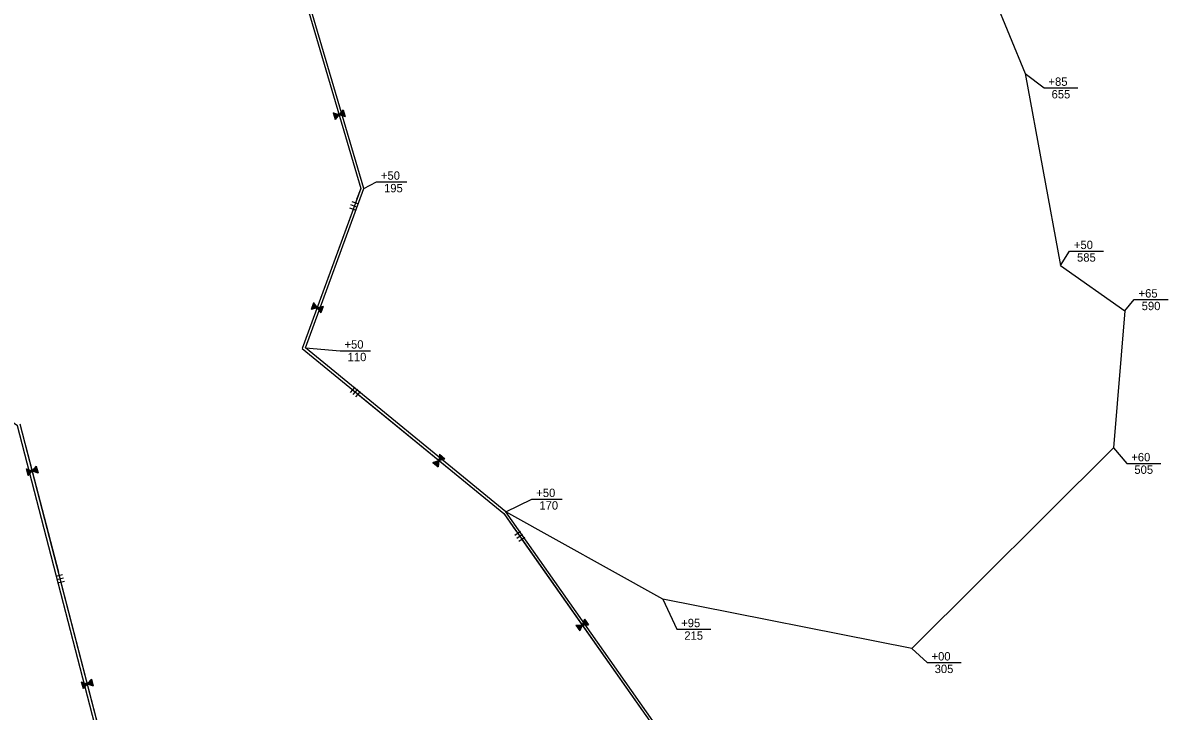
# Model space of a CAD drawing. Extents: x 979729 to 993523, y 1834148 to 1845433.
# Drawn here: x 980605 to 981425, y 1838851 to 1839343 of the extents above; entities that cross this region are included whole.
import ezdxf

# ---------------------------------------------------------------- set-up
doc = ezdxf.new("R2010")
doc.units = 0
for name, color, linetype in [('42', 7, 'Continuous'), ('51', 7, 'Continuous'), ('53', 7, 'Continuous'), ('R_Draft', 7, 'Continuous')]:
    doc.layers.add(name, color=color, linetype=linetype)

msp = doc.modelspace()

# ---------------------------------------------------------------- linework, layer by layer
at = {"layer": '42'}
for p, q in [((980795.43, 1839399), (980846.56, 1839224.93)), ((980833.94, 1839281.23), (980831.04, 1839277.77)), ((980832.76, 1839279.68), (980834.4, 1839279.17)), ((980832.86, 1839279.91), (980834.47, 1839279.41)), ((980833.01, 1839280.12), (980834.38, 1839279.69)), ((980833.2, 1839280.33), (980834.3, 1839279.98)), ((980833.4, 1839280.53), (980834.22, 1839280.27)), ((980833.55, 1839280.74), (980834.13, 1839280.56)), ((980833.75, 1839280.94), (980834.05, 1839280.85)), ((980833.9, 1839281.16), (980833.96, 1839281.14)), ((980826.74, 1839279.11), (980831.04, 1839277.77)), ((980826.81, 1839279.07), (980826.77, 1839279.02)), ((980827.05, 1839278.98), (980826.85, 1839278.73)), ((980827.32, 1839278.91), (980826.93, 1839278.45)), ((980827.57, 1839278.81), (980827.02, 1839278.16)), ((980827.84, 1839278.75), (980827.1, 1839277.87)), ((980828.11, 1839278.68), (980827.19, 1839277.58)), ((980828.36, 1839278.59), (980827.27, 1839277.29)), ((980828.86, 1839278.41), (980827.44, 1839276.72)), ((980828.56, 1839278.44), (980827.47, 1839277.13)), ((980829.1, 1839278.31), (980827.53, 1839276.43)), ((980829.39, 1839278.27), (980827.61, 1839276.14)), ((980829.62, 1839278.15), (980827.7, 1839275.85)), ((980829.91, 1839278.1), (980827.78, 1839275.56)), ((980830.15, 1839278.01), (980827.87, 1839275.28)), ((980830.43, 1839277.94), (980827.95, 1839274.99)), ((980830.65, 1839277.82), (980828.04, 1839274.7)), ((980830.94, 1839277.78), (980828.12, 1839274.41)), ((980831.04, 1839277.77), (980828.15, 1839274.31)), ((980831.04, 1839277.77), (980835.34, 1839276.43)), ((980831.12, 1839277.83), (980835.32, 1839276.52)), ((980831.34, 1839278.03), (980835.23, 1839276.81)), ((980831.47, 1839278.25), (980835.15, 1839277.1)), ((980831.66, 1839278.45), (980835.06, 1839277.39)), ((980831.81, 1839278.66), (980834.98, 1839277.68)), ((980832.03, 1839278.86), (980834.89, 1839277.96)), ((980832.16, 1839279.08), (980834.81, 1839278.25)), ((980832.38, 1839279.27), (980834.72, 1839278.54)), ((980832.54, 1839279.49), (980834.64, 1839278.83)), ((980846.56, 1839224.93), (980804.71, 1839110.23)), ((980845.13, 1839213.72), (980840.44, 1839215.43)), ((980843.42, 1839209.02), (980838.72, 1839210.73)), ((980844.28, 1839211.37), (980839.58, 1839213.08)), ((980814.79, 1839140.14), (980811.32, 1839139.3)), ((980814.65, 1839140.36), (980811.43, 1839139.58)), ((980814.44, 1839140.57), (980811.53, 1839139.86)), ((980814.33, 1839140.8), (980811.63, 1839140.15)), ((980814.12, 1839141.01), (980811.74, 1839140.43)), ((980813.98, 1839141.23), (980811.84, 1839140.71)), ((980813.69, 1839141.67), (980812.05, 1839141.27)), ((980813.76, 1839141.43), (980812.1, 1839141.03)), ((980813.55, 1839141.9), (980812.15, 1839141.56)), ((980813.37, 1839142.11), (980812.25, 1839141.84)), ((980813.19, 1839142.32), (980812.35, 1839142.12)), ((980813.05, 1839142.55), (980812.46, 1839142.4)), ((980812.87, 1839142.76), (980812.56, 1839142.69)), ((980812.73, 1839142.98), (980812.66, 1839142.97)), ((980812.7, 1839143.06), (980815.36, 1839139.42)), ((980819.74, 1839140.48), (980815.36, 1839139.42)), ((980818.34, 1839140.14), (980819.19, 1839138.99)), ((980818.62, 1839140.19), (980819.3, 1839139.27)), ((980818.89, 1839140.24), (980819.4, 1839139.55)), ((980819.14, 1839140.32), (980819.5, 1839139.83)), ((980819.42, 1839140.37), (980819.61, 1839140.11)), ((980819.67, 1839140.45), (980819.71, 1839140.4)), ((980815.36, 1839139.42), (980810.98, 1839138.36)), ((980815.29, 1839139.49), (980811.02, 1839138.45)), ((980815.08, 1839139.7), (980811.12, 1839138.73)), ((980814.97, 1839139.93), (980811.22, 1839139.02)), ((980815.36, 1839139.42), (980818.03, 1839135.79)), ((980815.46, 1839139.43), (980818.06, 1839135.88)), ((980815.75, 1839139.45), (980818.16, 1839136.16)), ((980815.99, 1839139.55), (980818.27, 1839136.45)), ((980816.26, 1839139.6), (980818.37, 1839136.73)), ((980816.51, 1839139.68), (980818.47, 1839137.01)), ((980816.81, 1839139.71), (980818.58, 1839137.29)), ((980817.04, 1839139.81), (980818.68, 1839137.57)), ((980817.33, 1839139.83), (980818.78, 1839137.86)), ((980817.58, 1839139.92), (980818.88, 1839138.14)), ((980817.88, 1839139.93), (980818.89, 1839138.56)), ((980818.09, 1839140.07), (980819.09, 1839138.7)), ((980804.71, 1839110.23), (980948.94, 1838992.15)), ((980842.22, 1839082.76), (980839.05, 1839078.89)), ((980844.15, 1839081.17), (980840.98, 1839077.3)), ((980846.09, 1839079.59), (980842.92, 1839075.72)), ((980602.52, 1839056.31), (980666.52, 1838809.33)), ((980902.98, 1839034.63), (980902.53, 1839030.14)), ((980902.84, 1839033.2), (980904.21, 1839033.62)), ((980902.88, 1839033.47), (980903.98, 1839033.81)), ((980902.93, 1839034.01), (980903.51, 1839034.19)), ((980902.93, 1839033.75), (980903.75, 1839034)), ((980902.98, 1839034.29), (980903.28, 1839034.38)), ((980902.99, 1839034.55), (980903.05, 1839034.57)), ((980614.22, 1839026.14), (980611.21, 1839022.78)), ((980613.66, 1839025.46), (980614.46, 1839025.18)), ((980613.82, 1839025.67), (980614.39, 1839025.47)), ((980614.02, 1839025.86), (980614.31, 1839025.76)), ((980614.18, 1839026.07), (980614.24, 1839026.05)), ((980898.22, 1839028.83), (980902.53, 1839030.14)), ((980898.3, 1839028.83), (980898.3, 1839028.77)), ((980898.56, 1839028.89), (980898.53, 1839028.58)), ((980898.82, 1839028.99), (980898.76, 1839028.39)), ((980899.08, 1839029.05), (980898.99, 1839028.2)), ((980899.34, 1839029.15), (980899.23, 1839028.01)), ((980899.6, 1839029.25), (980899.46, 1839027.81)), ((980899.86, 1839029.31), (980899.69, 1839027.62)), ((980900.11, 1839029.3), (980899.94, 1839027.6)), ((980900.37, 1839029.44), (980900.16, 1839027.24)), ((980900.63, 1839029.49), (980900.39, 1839027.05)), ((980900.89, 1839029.62), (980900.62, 1839026.86)), ((980901.15, 1839029.65), (980900.85, 1839026.67)), ((980901.41, 1839029.78), (980901.09, 1839026.48)), ((980901.67, 1839029.84), (980901.32, 1839026.29)), ((980901.93, 1839029.94), (980901.55, 1839026.1)), ((980902.18, 1839029.97), (980901.78, 1839025.91)), ((980902.45, 1839030.1), (980902.02, 1839025.72)), ((980902.53, 1839030.14), (980902.09, 1839025.66)), ((980902.53, 1839030.14), (980906.84, 1839031.46)), ((980902.56, 1839030.24), (980906.77, 1839031.52)), ((980902.62, 1839030.78), (980906.3, 1839031.91)), ((980902.64, 1839030.52), (980906.53, 1839031.71)), ((980902.66, 1839031.05), (980906.07, 1839032.1)), ((980902.67, 1839031.32), (980905.84, 1839032.29)), ((980902.72, 1839031.86), (980905.37, 1839032.67)), ((980902.74, 1839031.6), (980905.61, 1839032.48)), ((980902.79, 1839032.14), (980905.14, 1839032.86)), ((980902.8, 1839032.4), (980904.91, 1839033.05)), ((980902.83, 1839032.93), (980904.44, 1839033.43)), ((980902.88, 1839032.69), (980904.52, 1839033.19)), ((980606.96, 1839024.26), (980611.21, 1839022.78)), ((980607.02, 1839024.22), (980606.98, 1839024.17)), ((980607.26, 1839024.11), (980607.05, 1839023.88)), ((980607.53, 1839024.04), (980607.13, 1839023.59)), ((980607.78, 1839023.94), (980607.2, 1839023.3)), ((980608.05, 1839023.86), (980607.28, 1839023.01)), ((980608.31, 1839023.79), (980607.36, 1839022.72)), ((980608.56, 1839023.68), (980607.43, 1839022.42)), ((980609.05, 1839023.49), (980607.58, 1839021.84)), ((980608.76, 1839023.53), (980607.62, 1839022.26)), ((980609.29, 1839023.38), (980607.66, 1839021.55)), ((980609.58, 1839023.33), (980607.73, 1839021.26)), ((980609.8, 1839023.2), (980607.81, 1839020.97)), ((980610.09, 1839023.15), (980607.88, 1839020.68)), ((980610.33, 1839023.05), (980607.96, 1839020.39)), ((980610.6, 1839022.97), (980608.03, 1839020.1)), ((980610.83, 1839022.85), (980608.11, 1839019.81)), ((980611.11, 1839022.79), (980608.18, 1839019.52)), ((980611.21, 1839022.78), (980608.21, 1839019.42)), ((980611.21, 1839022.78), (980615.47, 1839021.3)), ((980611.29, 1839022.84), (980615.44, 1839021.4)), ((980611.52, 1839023.03), (980615.37, 1839021.69)), ((980611.65, 1839023.25), (980615.29, 1839021.98)), ((980611.85, 1839023.44), (980615.22, 1839022.27)), ((980612.01, 1839023.65), (980615.14, 1839022.56)), ((980612.24, 1839023.83), (980615.07, 1839022.85)), ((980612.37, 1839024.05), (980614.99, 1839023.14)), ((980612.6, 1839024.24), (980614.92, 1839023.43)), ((980612.76, 1839024.45), (980614.84, 1839023.72)), ((980613, 1839024.63), (980614.61, 1839024.07)), ((980613.1, 1839024.86), (980614.69, 1839024.31)), ((980613.26, 1839025.07), (980614.62, 1839024.6)), ((980613.46, 1839025.27), (980614.54, 1839024.89)), ((980948.94, 1838992.15), (981085.01, 1838798.93)), ((980961.07, 1838979.26), (980956.99, 1838976.38)), ((980962.51, 1838977.22), (980958.43, 1838974.34)), ((980963.95, 1838975.17), (980959.87, 1838972.29)), ((980633.07, 1838948.39), (980628.23, 1838947.13)), ((980633.7, 1838945.97), (980628.86, 1838944.71)), ((980634.33, 1838943.55), (980629.49, 1838942.29)), ((981000.59, 1838912.3), (981005.09, 1838912.41)), ((981000.67, 1838912.28), (981000.64, 1838912.22)), ((981000.93, 1838912.27), (981000.81, 1838911.98)), ((981001.21, 1838912.3), (981000.99, 1838911.73)), ((981001.47, 1838912.28), (981001.16, 1838911.48)), ((981001.75, 1838912.31), (981001.33, 1838911.24)), ((981002.03, 1838912.33), (981001.51, 1838910.99)), ((981002.29, 1838912.32), (981001.68, 1838910.75)), ((981002.53, 1838912.25), (981001.91, 1838910.66)), ((981002.82, 1838912.31), (981002.03, 1838910.26)), ((981003.08, 1838912.3), (981002.2, 1838910.01)), ((981003.37, 1838912.35), (981002.37, 1838909.77)), ((981003.63, 1838912.31), (981002.54, 1838909.52)), ((981003.91, 1838912.36), (981002.72, 1838909.27)), ((981004.18, 1838912.35), (981002.89, 1838909.03)), ((981004.45, 1838912.38), (981003.06, 1838908.78)), ((981004.71, 1838912.34), (981003.24, 1838908.54)), ((981005, 1838912.39), (981003.41, 1838908.29)), ((981005.09, 1838912.41), (981003.47, 1838908.21)), ((981006.72, 1838916.62), (981005.09, 1838912.41)), ((981005.09, 1838912.41), (981009.6, 1838912.53)), ((981005.15, 1838912.5), (981009.54, 1838912.61)), ((981005.29, 1838912.75), (981009.37, 1838912.86)), ((981005.34, 1838913), (981009.19, 1838913.1)), ((981005.46, 1838913.26), (981009.02, 1838913.35)), ((981005.54, 1838913.51), (981008.85, 1838913.59)), ((981005.68, 1838913.76), (981008.68, 1838913.84)), ((981005.73, 1838914.01), (981008.5, 1838914.08)), ((981005.88, 1838914.27), (981008.33, 1838914.33)), ((981005.96, 1838914.52), (981008.16, 1838914.57)), ((981006.11, 1838914.77), (981007.82, 1838914.82)), ((981006.12, 1838915.02), (981007.81, 1838915.07)), ((981006.2, 1838915.28), (981007.64, 1838915.31)), ((981006.32, 1838915.53), (981007.47, 1838915.56)), ((981006.44, 1838915.78), (981007.29, 1838915.8)), ((981006.51, 1838916.03), (981007.12, 1838916.05)), ((981006.63, 1838916.29), (981006.95, 1838916.29)), ((981006.71, 1838916.54), (981006.77, 1838916.54)), ((980646.46, 1838871.8), (980650.72, 1838870.32)), ((980646.53, 1838871.75), (980646.49, 1838871.71)), ((980646.77, 1838871.65), (980646.56, 1838871.41)), ((980647.04, 1838871.58), (980646.64, 1838871.12)), ((980647.28, 1838871.47), (980646.71, 1838870.83)), ((980647.55, 1838871.4), (980646.79, 1838870.54)), ((980647.82, 1838871.32), (980646.86, 1838870.25)), ((980648.06, 1838871.22), (980646.94, 1838869.96)), ((980648.56, 1838871.02), (980647.09, 1838869.38)), ((980648.26, 1838871.07), (980647.13, 1838869.79)), ((980648.8, 1838870.92), (980647.16, 1838869.09)), ((980649.09, 1838870.86), (980647.24, 1838868.8)), ((980649.31, 1838870.74), (980647.32, 1838868.51)), ((980649.6, 1838870.69), (980647.39, 1838868.22)), ((980649.84, 1838870.58), (980647.47, 1838867.92)), ((980650.11, 1838870.51), (980647.54, 1838867.63)), ((980650.33, 1838870.38), (980647.62, 1838867.34)), ((980650.62, 1838870.33), (980647.69, 1838867.05)), ((980650.72, 1838870.32), (980647.72, 1838866.96)), ((980653.72, 1838873.68), (980650.72, 1838870.32)), ((980650.72, 1838870.32), (980654.98, 1838868.84)), ((980650.8, 1838870.38), (980654.95, 1838868.93)), ((980651.03, 1838870.56), (980654.88, 1838869.22)), ((980651.16, 1838870.78), (980654.8, 1838869.52)), ((980651.36, 1838870.98), (980654.73, 1838869.81)), ((980651.52, 1838871.18), (980654.65, 1838870.1)), ((980651.75, 1838871.37), (980654.58, 1838870.39)), ((980651.88, 1838871.59), (980654.5, 1838870.68)), ((980652.11, 1838871.77), (980654.42, 1838870.97)), ((980652.27, 1838871.98), (980654.35, 1838871.26)), ((980652.5, 1838872.17), (980654.12, 1838871.61)), ((980652.6, 1838872.4), (980654.2, 1838871.84)), ((980652.77, 1838872.6), (980654.12, 1838872.13)), ((980652.96, 1838872.8), (980654.05, 1838872.42)), ((980653.16, 1838872.99), (980653.97, 1838872.71)), ((980653.32, 1838873.2), (980653.9, 1838873.01)), ((980653.52, 1838873.4), (980653.82, 1838873.3)), ((980653.69, 1838873.61), (980653.75, 1838873.59))]:
    msp.add_line(p, q, dxfattribs=at)
for points in [[(980795.43, 1839399), (980846.56, 1839224.93), (980843.64, 1839216.92)], [(980833.94, 1839281.23), (980835.34, 1839276.43)], [(980826.74, 1839279.11), (980828.15, 1839274.31)], [(980841.07, 1839209.88), (980804.71, 1839110.23), (980838.7, 1839082.4)], [(980812.7, 1839143.06), (980810.98, 1839138.36)], [(980819.74, 1839140.48), (980818.03, 1839135.79)], [(980844.5, 1839077.65), (980948.94, 1838992.15), (980957.59, 1838979.87)], [(980606.78, 1839039.89), (980630.03, 1838950.18)], [(980902.98, 1839034.63), (980906.84, 1839031.46)], [(980614.22, 1839026.14), (980615.47, 1839021.3)], [(980898.22, 1839028.83), (980902.09, 1839025.66)], [(980606.96, 1839024.26), (980608.21, 1839019.42)], [(980961.91, 1838973.73), (981048.28, 1838851.09)], [(980631.91, 1838942.92), (980666.52, 1838809.33), (980676.87, 1838803.26)], [(981000.59, 1838912.3), (981003.47, 1838908.21)], [(981006.72, 1838916.62), (981009.6, 1838912.53)], [(980646.46, 1838871.8), (980647.72, 1838866.96)], [(980653.72, 1838873.68), (980654.98, 1838868.84)]]:
    msp.add_lwpolyline(points, dxfattribs=at)
at = {"layer": '51'}
for points in [[(981283.24, 1838700.78), (981086.36, 1838800.49), (980950.42, 1838993.53), (980807.07, 1839110.88), (980848.67, 1839224.86), (980797.29, 1839399.75), (980720.77, 1839546.09), (980670.44, 1839600), (980680.38, 1839785.81), (980716.72, 1839906.34), (980844, 1840139.1), (980902.98, 1840283.23), (980949.95, 1840308.02)], [(980994.38, 1838500.84), (980945.96, 1838605.29), (980733.5, 1838767.74), (980664.8, 1838808.02), (980600.77, 1839055.1), (980508.89, 1839119.18), (980481.43, 1839200.1), (980412.37, 1839340.62)]]:
    msp.add_lwpolyline(points, dxfattribs=at)
at = {"layer": '53'}
for p, q in [((981220.87, 1839553.5), (981322.35, 1839307.27)), ((981322.35, 1839307.27), (981347.67, 1839169.72)), ((981347.67, 1839169.72), (981393.65, 1839137.33)), ((981393.65, 1839137.33), (981385.56, 1839039.32)), ((981385.56, 1839039.32), (981241.27, 1838895.59)), ((981062.86, 1838931.01), (980950.42, 1838993.53)), ((981241.27, 1838895.59), (981062.86, 1838931.01))]:
    msp.add_line(p, q, dxfattribs=at)
at = {"layer": 'R_Draft'}
for p, q in [((981341.85, 1839296.86), (981360.16, 1839296.86)), ((980863.86, 1839229.65), (980879.66, 1839229.65)), ((981360.08, 1839180.02), (981378.39, 1839180.02)), ((981406.37, 1839145.3), (981424.68, 1839145.3)), ((980837.78, 1839108.76), (980853.58, 1839108.76)), ((981401.15, 1839028.1), (981419.46, 1839028.1)), ((980975.09, 1839002.51), (980990.89, 1839002.51)), ((981078.88, 1838909.36), (981097.19, 1838909.36)), ((981258.12, 1838885.5), (981276.44, 1838885.5))]:
    msp.add_line(p, q, dxfattribs=at)
for points in [[(981322.35, 1839307.27), (981335.85, 1839296.86), (981341.85, 1839296.86)], [(980848.67, 1839224.86), (980857.86, 1839229.65), (980863.86, 1839229.65)], [(981347.67, 1839169.72), (981354.08, 1839180.02), (981360.08, 1839180.02)], [(981393.65, 1839137.33), (981400.37, 1839145.3), (981406.37, 1839145.3)], [(980807.07, 1839110.88), (980831.78, 1839108.76), (980837.78, 1839108.76)], [(981385.56, 1839039.32), (981395.15, 1839028.1), (981401.15, 1839028.1)], [(980950.42, 1838993.53), (980969.09, 1839002.51), (980975.09, 1839002.51)], [(981062.86, 1838931.01), (981072.88, 1838909.36), (981078.88, 1838909.36)], [(981241.27, 1838895.59), (981252.12, 1838885.5), (981258.12, 1838885.5)]]:
    msp.add_lwpolyline(points, dxfattribs=at)

# ---------------------------------------------------------------- texts
for s, p in [('+85', (981339.02, 1839298.36)), (' 655', (981339.02, 1839289.36)), ('+50', (980861.03, 1839231.15)), (' 195', (980861.03, 1839222.15)), ('+50', (981357.25, 1839181.52)), (' 585', (981357.25, 1839172.52)), ('+65', (981403.54, 1839146.8)), (' 590', (981403.54, 1839137.8)), ('+50', (980834.95, 1839110.26)), (' 110', (980834.95, 1839101.26)), ('+60', (981398.32, 1839029.6)), (' 505', (981398.32, 1839020.6)), ('+50', (980972.26, 1839004.01)), (' 170', (980972.26, 1838995.01)), ('+95', (981076.05, 1838910.86)), (' 215', (981076.05, 1838901.86)), ('+00', (981255.3, 1838887)), (' 305', (981255.3, 1838878))]:
    msp.add_text(s, height=6, rotation=360, dxfattribs=at).set_placement(p)

doc.saveas('drawing.dxf')
